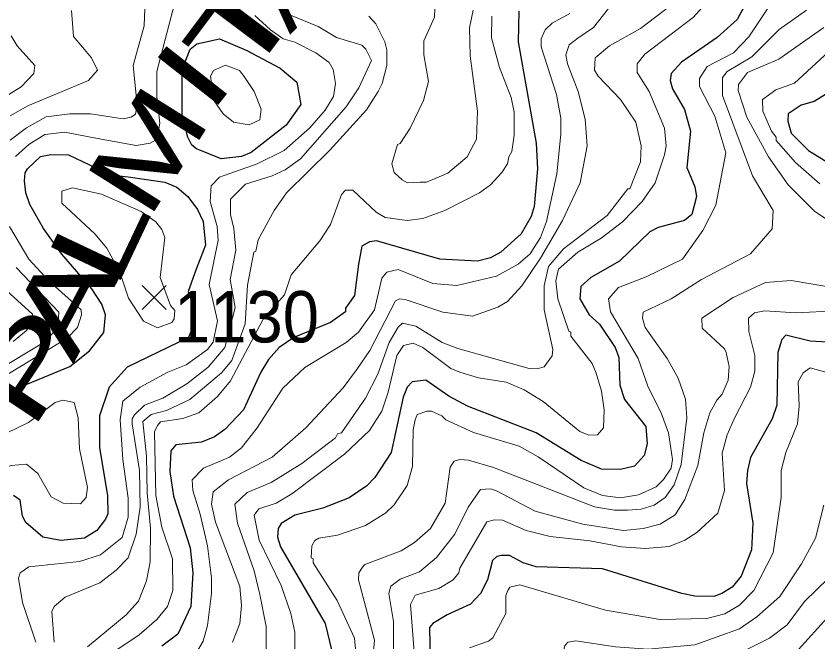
# Model space of a CAD drawing. Extents: x 423 to 448.8, y 7456.3 to 7484.
# Drawn here: x 427.369 to 428.618, y 7461.22 to 7462.195 of the extents above; entities that cross this region are included whole.
import ezdxf
from ezdxf.enums import TextEntityAlignment as Align

# ---------------------------------------------------------------- set-up
doc = ezdxf.new("R2010")
doc.units = 0
doc.header["$LTSCALE"] = 0.032
for name, color, linetype, lineweight in [('1', 7, 'Continuous', 25), ('2', 7, 'Continuous', 13), ('21', 7, 'Continuous', 25)]:
    doc.layers.add(name, color=color, linetype=linetype, lineweight=lineweight)
doc.layers.add('61', color=7, linetype='Continuous')

msp = doc.modelspace()

# ---------------------------------------------------------------- linework, layer by layer
at = {"layer": '1'}
for points in [[(428.5071, 7462.2169), (428.4924, 7462.1897), (428.4614, 7462.1619)], [(428.1521, 7462.2029), (428.1513, 7462.155)], [(428.1513, 7462.155), (428.1791, 7461.9972), (428.1814, 7461.957), (428.176, 7461.8982), (428.1714, 7461.8827), (428.1559, 7461.8556), (428.1242, 7461.827), (428.108, 7461.8185), (428.0879, 7461.8131), (428.0291, 7461.8162), (427.9301, 7461.8448), (427.9192, 7461.8433), (427.9076, 7461.8363), (427.9022, 7461.8085), (427.896, 7461.7597), (427.8821, 7461.7396), (427.8821, 7461.7342), (427.8589, 7461.7172), (427.8017, 7461.694), (427.7785, 7461.6785), (427.7622, 7461.66), (427.7498, 7461.6399), (427.7228, 7461.5811), (427.6941, 7461.5509), (427.6779, 7461.5393), (427.6578, 7461.5308), (427.6176, 7461.5269), (427.6099, 7461.5176), (427.6083, 7461.4852), (427.6137, 7461.4465), (427.64, 7461.366), (427.6439, 7461.3274), (427.6408, 7461.2747), (427.6207, 7461.2315), (427.5959, 7461.2129)], [(428.4614, 7462.1619), (428.4057, 7462.1232), (428.3895, 7462.1054), (428.3879, 7462.0946), (428.3918, 7462.0815), (428.4104, 7462.0497), (428.4197, 7462.0158), (428.4143, 7461.9593), (428.4266, 7461.9291), (428.429, 7461.9137), (428.422, 7461.8858), (428.4104, 7461.8765), (428.3694, 7461.8657), (428.3562, 7461.8587), (428.3091, 7461.8131), (428.2642, 7461.7875), (428.2487, 7461.7736), (428.2472, 7461.7543), (428.2619, 7461.7296), (428.2781, 7461.7149), (428.3021, 7461.6785), (428.3083, 7461.6631), (428.3098, 7461.6197), (428.3168, 7461.5973), (428.3501, 7461.5555), (428.3524, 7461.5285), (428.3477, 7461.5099), (428.3323, 7461.4936), (428.3106, 7461.4882), (428.2812, 7461.489), (428.2495, 7461.5022), (428.1791, 7461.5454), (428.0724, 7461.5872), (428.043, 7461.6027), (428.0074, 7461.6275), (427.9858, 7461.6251), (427.978, 7461.6166), (427.9718, 7461.6012), (427.9533, 7461.5146), (427.9277, 7461.4758), (427.9154, 7461.4627), (427.8875, 7461.4442), (427.8466, 7461.4279), (427.8032, 7461.4171), (427.7815, 7461.4039), (427.7769, 7461.3962), (427.7762, 7461.3831), (427.7808, 7461.3676), (427.8504, 7461.2485), (427.8605, 7461.2052)], [(428.6479, 7462.0838), (428.6123, 7462.0621), (428.5922, 7462.056), (428.572, 7462.0428), (428.5713, 7462.0312), (428.5767, 7462.0126), (428.6037, 7461.9856), (428.719, 7461.9144)], [(427.3423, 7461.6035), (427.4521, 7461.6491), (427.483, 7461.6731), (427.5054, 7461.7017), (427.5078, 7461.7296), (427.5023, 7461.7458), (427.4869, 7461.7698), (427.4397, 7461.8239), (427.4111, 7461.8642), (427.3902, 7461.9013), (427.384, 7461.9198), (427.3817, 7461.9384), (427.3825, 7461.9507), (427.3863, 7461.957), (427.4064, 7461.9763), (427.4227, 7461.9794), (427.4505, 7461.9786), (427.5155, 7461.9477), (427.5434, 7461.9445), (427.6006, 7461.936), (427.6192, 7461.9283), (427.6361, 7461.9136), (427.6516, 7461.8935), (427.6601, 7461.875), (427.664, 7461.8379), (427.6493, 7461.8007), (427.6367, 7461.7659), (427.6441, 7461.7451), (427.6459, 7461.7282), (427.6424, 7461.7073), (427.6371, 7461.6939), (427.5418, 7461.6476), (427.5139, 7461.6166), (427.4985, 7461.5718), (427.4985, 7461.5223), (427.5109, 7461.448), (427.5116, 7461.4194), (427.5078, 7461.4109), (427.4946, 7461.3931), (427.4753, 7461.3815), (427.4382, 7461.3776), (427.4103, 7461.383), (427.384, 7461.4055), (427.3786, 7461.4155), (427.3747, 7461.4403), (427.3646, 7461.448)], [(428.6881, 7461.6839), (428.6061, 7461.6886), (428.5682, 7461.6978), (428.562, 7461.6909), (428.5558, 7461.6708), (428.5543, 7461.5888), (428.5473, 7461.5671), (428.5133, 7461.5068), (428.5086, 7461.4867), (428.5071, 7461.4666), (428.5171, 7461.4047), (428.5148, 7461.363), (428.4986, 7461.3219), (428.4846, 7461.3049), (428.4684, 7461.2949), (428.456, 7461.2902), (428.4266, 7461.291), (428.4065, 7461.2948), (428.2828, 7461.3335), (428.1791, 7461.3366), (428.159, 7461.3428), (428.1374, 7461.3544), (428.125, 7461.3544), (428.118, 7461.3529), (428.111, 7461.3467), (428.1033, 7461.3165), (428.0925, 7461.2949), (428.077, 7461.2786), (428.0407, 7461.2616), (428.0182, 7461.2485), (428.0128, 7461.2423), (428.0144, 7461.1665)]]:
    msp.add_lwpolyline(points, dxfattribs=at)
msp.add_lwpolyline([(427.64, 7462.1433), (427.6501, 7462.1519), (427.6856, 7462.1596), (427.7274, 7462.1418), (427.78, 7462.1139), (427.8063, 7462.0923), (427.8125, 7462.0575), (427.7893, 7462.025), (427.7351, 7461.9825), (427.7197, 7461.9763), (427.688, 7461.9724), (427.65, 7461.9879), (427.6423, 7461.9941), (427.6362, 7462.0065), (427.6276, 7462.0405), (427.6276, 7462.1117)], close=True, dxfattribs=at)
at = {"layer": '2'}
for points in [[(427.3677, 7461.9763), (427.3887, 7461.9949), (427.4134, 7462.0103), (427.4444, 7462.0142), (427.4954, 7462.0041), (427.5557, 7461.9933), (427.5774, 7461.9972), (427.5859, 7462.0018), (427.589, 7462.008), (427.5928, 7462.0281), (427.5882, 7462.0699), (427.5882, 7462.1086), (427.6253, 7462.2524)], [(428.5682, 7462.2493), (428.5109, 7462.1627), (428.487, 7462.1379), (428.446, 7462.1163), (428.4336, 7462.0977), (428.4336, 7462.0853), (428.4575, 7462.039), (428.4746, 7461.9817), (428.4591, 7461.9005), (428.439, 7461.8611), (428.4073, 7461.8162), (428.3508, 7461.7884), (428.3075, 7461.7721), (428.2921, 7461.7543), (428.2951, 7461.7342), (428.3384, 7461.6615), (428.3531, 7461.6182), (428.3748, 7461.5749), (428.3856, 7461.5455), (428.3918, 7461.5037), (428.3895, 7461.4905), (428.3779, 7461.4728), (428.3663, 7461.4612), (428.3385, 7461.4488), (428.3106, 7461.4441), (428.2828, 7461.448), (428.2534, 7461.4596), (428.1822, 7461.5083), (428.1528, 7461.5246), (428.0817, 7461.5462), (428.0384, 7461.5656), (428.0322, 7461.5718), (428.0159, 7461.5795), (428.009, 7461.5795), (427.9935, 7461.5741), (427.9904, 7461.5656), (427.9873, 7461.5501), (427.9865, 7461.4929), (427.978, 7461.4635), (427.9579, 7461.4333), (427.9448, 7461.4209), (427.9131, 7461.4008), (427.8698, 7461.3862), (427.8404, 7461.3815), (427.8341, 7461.3776), (427.8295, 7461.3691), (427.8287, 7461.3505), (427.8318, 7461.349), (427.8318, 7461.3428), (427.869, 7461.2841), (427.896, 7461.2253), (427.9007, 7461.175)], [(427.5696, 7462.2215), (427.5681, 7462.1797), (427.5511, 7462.1179), (427.5573, 7462.056), (427.5549, 7462.042), (427.548, 7462.0374), (427.5356, 7462.0351), (427.4846, 7462.0428), (427.4521, 7462.0428), (427.4157, 7462.0382), (427.3848, 7462.0211), (427.3592, 7462.0018)], [(427.7057, 7461.2191), (427.7174, 7461.2485), (427.7197, 7461.2763), (427.7174, 7461.3057), (427.6795, 7461.4063), (427.6733, 7461.4341), (427.6756, 7461.4534), (427.6995, 7461.472), (427.7677, 7461.5076), (427.8202, 7461.5532), (427.8782, 7461.6158), (427.9007, 7461.646), (427.92, 7461.6739), (427.9602, 7461.7512), (427.9664, 7461.7543), (427.9749, 7461.7535), (428.0337, 7461.7334), (428.0801, 7461.7272), (428.1196, 7461.7411), (428.1343, 7461.7504), (428.1567, 7461.7744), (428.1861, 7461.8177), (428.2201, 7461.8765), (428.2479, 7461.9353), (428.2588, 7461.9926), (428.2557, 7462.0343), (428.2449, 7462.0776), (428.2278, 7462.1209), (428.2255, 7462.1349), (428.2309, 7462.1503), (428.2441, 7462.1604), (428.2688, 7462.1774), (428.2998, 7462.2169)], [(428.2101, 7461.7822), (428.2139, 7461.8007), (428.2441, 7461.827), (428.2804, 7461.8487), (428.3137, 7461.8742), (428.3446, 7461.9059), (428.3647, 7461.9353), (428.3794, 7461.9786), (428.3817, 7461.9926), (428.3794, 7462.0204), (428.3554, 7462.0776), (428.3369, 7462.107), (428.3369, 7462.1209), (428.3485, 7462.1356), (428.4243, 7462.1936), (428.4467, 7462.2184)], [(427.4552, 7462.2037), (427.4583, 7462.1635), (427.4861, 7462.1302), (427.4954, 7462.1109), (427.4814, 7462.0946), (427.3871, 7462.0552), (427.3593, 7462.0397)], [(428.3895, 7462.2122), (428.3416, 7462.1758), (428.2936, 7462.1487), (428.2712, 7462.1302), (428.2704, 7462.1109), (428.2758, 7462.1016), (428.3106, 7462.0653), (428.3346, 7462.0297), (428.3431, 7461.9926), (428.3416, 7461.9678), (428.3253, 7461.926), (428.3222, 7461.926), (428.2897, 7461.8842), (428.2217, 7461.8324), (428.1984, 7461.8046), (428.1915, 7461.7744), (428.1915, 7461.7373), (428.2054, 7461.6754), (428.2039, 7461.6654), (428.1915, 7461.6483), (428.1806, 7461.6452), (428.1683, 7461.646), (428.0569, 7461.6769), (428.0329, 7461.6862), (427.9919, 7461.7118), (427.9711, 7461.7164), (427.9641, 7461.7102), (427.9502, 7461.6863), (427.9324, 7461.6368), (427.913, 7461.5996), (427.8759, 7461.5454), (427.8698, 7461.5439), (427.8667, 7461.5377), (427.8141, 7461.4975), (427.7661, 7461.4681), (427.729, 7461.4527), (427.7096, 7461.4341), (427.7135, 7461.4047), (427.7398, 7461.3305)], [(428.6007, 7462.2044), (428.5581, 7462.1743), (428.5156, 7462.1317), (428.4769, 7462.1085), (428.4699, 7462.0993), (428.4699, 7462.0714), (428.5163, 7461.9461), (428.5488, 7461.892), (428.5473, 7461.8633), (428.5133, 7461.8247), (428.4367, 7461.7845), (428.3895, 7461.7543), (428.3462, 7461.7334), (428.3447, 7461.7241), (428.3493, 7461.7095), (428.3833, 7461.6615), (428.4003, 7461.6306), (428.4119, 7461.5981), (428.4143, 7461.5687), (428.405, 7461.496), (428.3942, 7461.4643), (428.3802, 7461.4449), (428.3632, 7461.4326), (428.3431, 7461.4264), (428.3215, 7461.4248), (428.3013, 7461.4248), (428.2704, 7461.4302), (428.1126, 7461.4913), (428.0739, 7461.5029), (428.06, 7461.5037), (428.0515, 7461.5014), (428.0453, 7461.4921), (428.0376, 7461.4357), (428.0144, 7461.3962), (427.9896, 7461.3745), (427.9688, 7461.3614), (427.9123, 7461.3405), (427.9084, 7461.3359), (427.903, 7461.3274), (427.9022, 7461.3165), (427.927, 7461.2222), (427.9223, 7461.1711)], [(428.0809, 7462.2045), (428.0755, 7462.1766), (428.0762, 7462.1333), (428.0879, 7462.0467), (428.0863, 7462.0034), (428.0716, 7461.9755), (428.0415, 7461.95), (428.0082, 7461.9361), (427.9982, 7461.9361), (427.9788, 7461.9353), (427.9703, 7461.9399), (427.9579, 7461.9515), (427.954, 7461.9647), (427.9633, 7461.9948), (427.9672, 7461.9964), (427.9826, 7462.0204), (428.0035, 7462.0637), (428.0113, 7462.0931), (428.0043, 7462.1349), (428.0043, 7462.1565), (428.0205, 7462.1936), (428.0213, 7462.2076)], [(428.1103, 7462.1952), (428.1095, 7462.1612), (428.1219, 7462.1148), (428.1404, 7462.0683), (428.1451, 7462.0451), (428.1451, 7462.0096), (428.1412, 7461.984), (428.1366, 7461.9755), (428.1343, 7461.9647), (428.1257, 7461.9515), (428.108, 7461.9322), (428.091, 7461.9198), (428.0368, 7461.892), (428.0028, 7461.8796), (427.978, 7461.8765), (427.944, 7461.8812), (427.93, 7461.8896), (427.8937, 7461.9237), (427.8821, 7461.9237), (427.8759, 7461.9168), (427.8589, 7461.8703), (427.8419, 7461.8448), (427.7975, 7461.7915), (427.7869, 7461.7608), (427.7539, 7461.7225), (427.7027, 7461.6267), (427.6825, 7461.6019), (427.6532, 7461.5764), (427.6284, 7461.5679), (427.5936, 7461.5625), (427.589, 7461.5571), (427.5843, 7461.547), (427.5866, 7461.448), (427.5959, 7461.3985), (427.6122, 7461.349), (427.613, 7461.2995), (427.6044, 7461.2748), (427.5882, 7461.2546), (427.5604, 7461.2307), (427.5225, 7461.2052)], [(428.2317, 7462.199), (428.2039, 7462.1841), (428.1931, 7462.1735), (428.1868, 7462.1596), (428.1868, 7462.1472), (428.2108, 7462.073), (428.2178, 7462.0359), (428.2178, 7462.0111), (428.2116, 7461.9492), (428.1954, 7461.875), (428.1861, 7461.8502), (428.1698, 7461.8247), (428.1513, 7461.8084), (428.1173, 7461.7899), (428.0554, 7461.7752), (428.0183, 7461.7783), (427.9641, 7461.7999), (427.9463, 7461.796), (427.9386, 7461.7868), (427.927, 7461.7373), (427.9022, 7461.7025), (427.8829, 7461.6863), (427.8187, 7461.6475), (427.7846, 7461.6151), (427.7444, 7461.5532), (427.7197, 7461.5222), (427.7011, 7461.5076), (427.6609, 7461.4906), (427.6431, 7461.472), (427.6439, 7461.4558), (427.6555, 7461.4186), (427.6671, 7461.3691), (427.6733, 7461.3196), (427.6733, 7461.2949), (427.6671, 7461.2454), (427.6601, 7461.2206), (427.6361, 7461.1804)], [(427.6941, 7461.6785), (427.7099, 7461.7409), (427.7024, 7461.7844), (427.7112, 7461.8301), (427.7081, 7461.8642), (427.7027, 7461.8858), (427.7027, 7461.9098), (427.7259, 7461.933), (427.7677, 7461.9461), (427.7878, 7461.9554), (427.8117, 7461.9724), (427.8829, 7462.0536), (427.903, 7462.083), (427.9223, 7462.1256), (427.9138, 7462.1433), (427.9076, 7462.1495), (427.8682, 7462.1619), (427.8396, 7462.1789), (427.7963, 7462.1967)], [(427.7406, 7462.1959), (427.7653, 7462.1735), (427.7847, 7462.1596), (427.8032, 7462.1542), (427.8357, 7462.138), (427.8566, 7462.1225), (427.8628, 7462.1117), (427.8667, 7462.09), (427.8635, 7462.0699)], [(427.746, 7461.8463), (427.7707, 7461.892), (427.7901, 7461.9198), (427.8574, 7461.9863), (427.9146, 7462.049), (427.9331, 7462.0776), (427.9393, 7462.09), (427.9463, 7462.1179), (427.9463, 7462.1426), (427.9432, 7462.155), (427.9293, 7462.1828), (427.9185, 7462.1952)], [(428.6277, 7462.1774), (428.5573, 7462.1279), (428.5086, 7462.107), (428.4947, 7462.0885), (428.4939, 7462.0792), (428.5078, 7462.0374), (428.5411, 7461.9755), (428.5721, 7461.9322), (428.613, 7461.8912), (428.7554, 7461.7961)], [(427.2897, 7462.0312), (427.3763, 7462.0846), (427.3964, 7462.1054), (427.3979, 7462.1179), (427.3701, 7462.1488), (427.3608, 7462.1642)], [(428.6617, 7462.1643), (428.5821, 7462.0907), (428.5527, 7462.0799), (428.5318, 7462.0652), (428.5326, 7462.0467), (428.5458, 7462.0157), (428.5535, 7462.0064), (428.5535, 7462.001), (428.5836, 7461.967), (428.6215, 7461.9338)], [(427.8635, 7462.0699), (427.8504, 7462.0482), (427.8264, 7462.0211), (427.7862, 7461.9856), (427.7445, 7461.9647), (427.6856, 7461.9438), (427.6725, 7461.9307), (427.6709, 7461.9059), (427.6818, 7461.8672), (427.6833, 7461.8456), (427.6696, 7461.7769)], [(427.3167, 7461.6135), (427.4482, 7461.6932), (427.4645, 7461.7095), (427.4706, 7461.7296), (427.4698, 7461.7373), (427.4196, 7461.7822), (427.3886, 7461.8162), (427.3585, 7461.8672)], [(427.4799, 7461.2121), (427.5403, 7461.2616), (427.5596, 7461.2833), (427.5719, 7461.315), (427.5774, 7461.3444), (427.5781, 7461.397), (427.5729, 7461.4519), (427.5721, 7461.5089), (427.5661, 7461.5629), (427.5789, 7461.5743), (427.6029, 7461.5803), (427.6392, 7461.5973), (427.6888, 7461.639), (427.705, 7461.6584), (427.7255, 7461.7155), (427.7293, 7461.7755), (427.739, 7461.827), (427.7421, 7461.8285), (427.746, 7461.8463)], [(427.3129, 7461.8038), (427.3941, 7461.7303), (427.394, 7461.7172), (427.3848, 7461.7048), (427.3639, 7461.6878)], [(427.3685, 7461.803), (427.4351, 7461.7334), (427.4335, 7461.7102), (427.4149, 7461.6885), (427.3345, 7461.6398)], [(427.6696, 7461.7769), (427.6824, 7461.7201), (427.6756, 7461.687), (427.6671, 7461.6754), (427.6338, 7461.6514), (427.6052, 7461.6398), (427.5619, 7461.6166), (427.5348, 7461.595), (427.531, 7461.5656), (427.5348, 7461.5037), (427.5434, 7461.4434), (427.5434, 7461.414), (427.5341, 7461.3823), (427.5, 7461.3552), (427.4676, 7461.3451), (427.3886, 7461.3366), (427.3747, 7461.3273), (427.3724, 7461.3188), (427.3786, 7461.281), (427.3995, 7461.2191)], [(427.8032, 7461.2067), (427.8032, 7461.2346), (427.797, 7461.264), (427.7816, 7461.3073), (427.7475, 7461.3784), (427.7398, 7461.417), (427.7468, 7461.4271), (427.7738, 7461.4357), (427.7986, 7461.4503), (427.8806, 7461.5122), (427.9192, 7461.5493), (427.9386, 7461.5795), (427.9486, 7461.6089), (427.9618, 7461.6662), (427.9726, 7461.6816), (427.9873, 7461.6855), (428.0028, 7461.6785), (428.0461, 7461.646), (428.06, 7461.6398), (428.0894, 7461.6313), (428.1327, 7461.6244), (428.1606, 7461.6127), (428.19, 7461.5942), (428.2472, 7461.5478), (428.2611, 7461.5416), (428.275, 7461.5424), (428.2843, 7461.5532), (428.2851, 7461.5811), (428.2812, 7461.6105), (428.2727, 7461.6383), (428.2665, 7461.6538), (428.2333, 7461.6963), (428.2333, 7461.7025), (428.2302, 7461.704), (428.2131, 7461.7543), (428.2101, 7461.7822)], [(428.7422, 7461.7551), (428.5767, 7461.7829), (428.5365, 7461.7798), (428.4862, 7461.7566), (428.4375, 7461.7241), (428.4382, 7461.7087), (428.473, 7461.6762), (428.4753, 7461.6708), (428.48, 7461.6491), (428.4784, 7461.6275), (428.4692, 7461.6058), (428.4606, 7461.5965), (428.4498, 7461.5764), (428.4406, 7461.5455), (428.4313, 7461.4944), (428.4112, 7461.4418), (428.3957, 7461.4178), (428.3725, 7461.4032), (428.3462, 7461.3962), (428.3153, 7461.3931), (428.2518, 7461.4032), (428.1776, 7461.4233), (428.1173, 7461.455), (428.108, 7461.4581), (428.0925, 7461.4573), (428.0731, 7461.4295), (428.0523, 7461.3877), (428.0237, 7461.3513), (427.9974, 7461.3289), (427.9672, 7461.3173), (427.9525, 7461.3065), (427.9494, 7461.2949), (427.9571, 7461.2516), (427.9571, 7461.2005)], [(428.6463, 7461.7358), (428.5844, 7461.7327), (428.5349, 7461.7358), (428.5195, 7461.7327), (428.5102, 7461.7241), (428.5109, 7461.7033), (428.5202, 7461.6662), (428.5202, 7461.6414), (428.5133, 7461.6166), (428.4877, 7461.5671), (428.4769, 7461.5424), (428.4692, 7461.5138), (428.473, 7461.4558), (428.4622, 7461.4201), (428.4297, 7461.39), (428.4112, 7461.3784), (428.3864, 7461.3683), (428.3493, 7461.3652), (428.3122, 7461.3676), (428.2627, 7461.3769), (428.2008, 7461.3838), (428.1637, 7461.3931), (428.1265, 7461.4094), (428.1142, 7461.4101), (428.1025, 7461.407), (428.06, 7461.3343), (428.0585, 7461.3273), (428.0499, 7461.3165), (428.0275, 7461.3026), (427.9904, 7461.2925), (427.9834, 7461.2779), (427.9889, 7461.2036)], [(427.4992, 7461.3119), (427.5247, 7461.3312), (427.5434, 7461.3505), (427.5557, 7461.3877), (427.5619, 7461.4295), (427.5611, 7461.4867), (427.5495, 7461.5594), (427.5495, 7461.5671), (427.5534, 7461.5733), (427.5689, 7461.5888), (427.5975, 7461.5996), (427.6346, 7461.622), (427.6679, 7461.6476), (427.6941, 7461.6785)], [(428.0755, 7461.2105), (428.1049, 7461.2206), (428.1118, 7461.226), (428.1319, 7461.2639), (428.1319, 7461.2918), (428.135, 7461.2995), (428.1381, 7461.3049), (428.1536, 7461.3088), (428.2874, 7461.2693), (428.3725, 7461.2547), (428.4452, 7461.2562), (428.4731, 7461.2631), (428.4963, 7461.2771), (428.5187, 7461.2995), (428.5488, 7461.3583), (428.5612, 7461.4449), (428.5612, 7461.4867), (428.5682, 7461.5146), (428.5867, 7461.5594), (428.5891, 7461.5873), (428.5875, 7461.6251), (428.5952, 7461.639), (428.6061, 7461.6468), (428.7066, 7461.6189)], [(428.6277, 7461.4326), (428.6146, 7461.3815), (428.5929, 7461.3412), (428.5589, 7461.2902), (428.5233, 7461.2585), (428.4963, 7461.2399), (428.4266, 7461.2152), (428.3539, 7461.2082), (428.3029, 7461.2121), (428.241, 7461.2214), (428.2286, 7461.2191), (428.2232, 7461.2129), (428.2209, 7461.1943), (428.2271, 7461.1804), (428.2263, 7461.1572), (428.2178, 7461.1463)], [(428.6726, 7461.356), (428.5975, 7461.2825), (428.5705, 7461.2461), (428.5427, 7461.2252), (428.5241, 7461.216), (428.4437, 7461.1758), (428.3957, 7461.1626), (428.3478, 7461.1634), (428.2874, 7461.1789), (428.2719, 7461.1773), (428.2665, 7461.168), (428.2689, 7461.1433), (428.2611, 7461.1332), (428.2487, 7461.1255), (428.2487, 7461.1185), (428.2611, 7461.0984), (428.2642, 7461.0984), (428.2711, 7461.083)], [(427.7398, 7461.3305), (427.7483, 7461.2933), (427.7584, 7461.2438), (427.7584, 7461.2067)], [(427.4281, 7461.2191), (427.4242, 7461.267), (427.4281, 7461.2747), (427.4451, 7461.2894), (427.4992, 7461.3119)], [(428.6486, 7461.274), (428.5728, 7461.1912)]]:
    msp.add_lwpolyline(points, dxfattribs=at)
for points in [[(427.6911, 7462.0428), (427.6771, 7462.0629), (427.6717, 7462.1016), (427.6764, 7462.1101), (427.6949, 7462.1186), (427.7166, 7462.1101), (427.7243, 7462.1008), (427.7398, 7462.0776), (427.7506, 7462.0498), (427.7483, 7462.0335), (427.7321, 7462.0258), (427.7073, 7462.0297)], [(427.6094, 7461.7442), (427.5929, 7461.7876), (427.6006, 7461.8502), (427.5959, 7461.8626), (427.5866, 7461.8742), (427.5635, 7461.8904), (427.5016, 7461.9175), (427.4567, 7461.9275), (427.4397, 7461.9221), (427.4397, 7461.9036), (427.4915, 7461.8556), (427.5101, 7461.8332), (427.5302, 7461.7961), (427.5439, 7461.7554), (427.5672, 7461.7195), (427.5889, 7461.709), (427.6115, 7461.7172), (427.6148, 7461.7232), (427.6159, 7461.7363)], [(427.3879, 7461.5617), (427.4296, 7461.5926), (427.4413, 7461.5965), (427.459, 7461.5927), (427.4652, 7461.5687), (427.4676, 7461.5207), (427.4799, 7461.4604), (427.4776, 7461.4449), (427.4691, 7461.4349), (427.442, 7461.4356), (427.4234, 7461.4457), (427.4025, 7461.4821), (427.3848, 7461.4967), (427.3608, 7461.4944), (427.3376, 7461.4859), (427.3129, 7461.4867), (427.3005, 7461.4928), (427.2974, 7461.5215), (427.3067, 7461.5339), (427.319, 7461.5393), (427.3546, 7461.5455)]]:
    msp.add_lwpolyline(points, close=True, dxfattribs=at)
at = {"layer": '21'}
for p, q in [((427.5652, 7461.7751), (427.6027, 7461.7376)), ((427.6027, 7461.7751), (427.5652, 7461.7376))]:
    msp.add_line(p, q, dxfattribs=at)

# ---------------------------------------------------------------- texts
at = {"layer": '61'}
msp.add_text('A', height=0.12, rotation=45, dxfattribs=at).set_placement((427.8333, 7462.2035), align=Align.CENTER)
for s, rotation, width, p in [('T', 53.13, 1.8, (427.7717, 7462.1486)), ('I', 51.843, 1.45, (427.6906, 7462.0654)), ('M', 57.794, 1.4, (427.6242, 7461.9544)), ('L', 64.696, 1.55, (427.5524, 7461.8278)), ('A', 61.902, 1.5, (427.4952, 7461.7227)), ('P', 56.33, 1.6, (427.4394, 7461.6171))]:
    msp.add_text(s, height=0.12, rotation=rotation, dxfattribs=dict(at, width=width)).set_placement(p, align=Align.CENTER)
at = {"layer": '61', "width": 0.95}
msp.add_text('1130', height=0.08, dxfattribs=at).set_placement((427.7277, 7461.6864), align=Align.CENTER)

doc.saveas('drawing.dxf')
